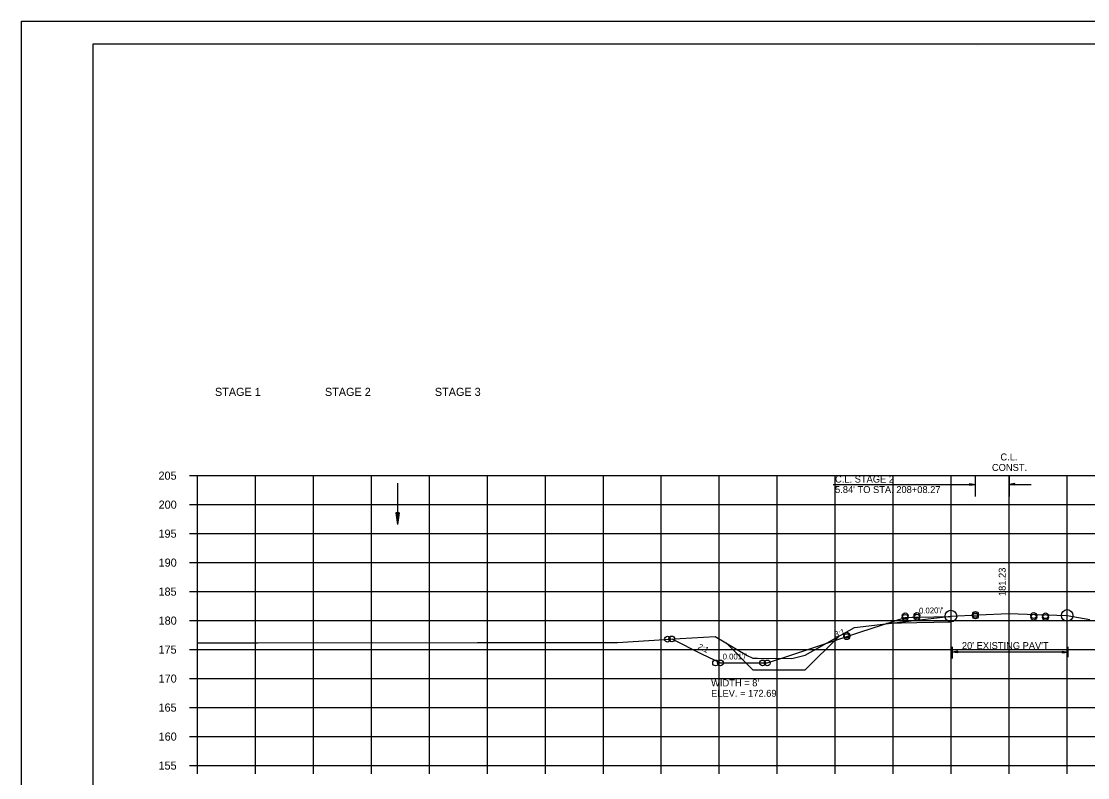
# Model space of a CAD drawing. Extents: x 1372132 to 1372465, y 380083 to 381790.
# Drawn here: x 1372131.6 to 1372315.6, y 381446.4 to 381576.9 of the extents above; entities that cross this region are included whole.
import ezdxf

# ---------------------------------------------------------------- set-up
doc = ezdxf.new("R2010")
doc.units = 0
for name, color, linetype in [('R_Alt Surface', 7, 'Continuous'), ('R_Axis', 7, 'Continuous'), ('R_Axis Annot', 7, 'Continuous'), ('R_Border', 7, 'Continuous'), ('R_Dimension', 7, 'Continuous'), ('R_Draft', 7, 'Continuous'), ('R_Erosion', 7, 'Continuous'), ('R_Exist Surface', 7, 'Continuous'), ('R_Fin Surface', 7, 'Continuous'), ('R_Grid', 7, 'Continuous'), ('R_No Plot', 7, 'Continuous'), ('R_Xsect Elev', 7, 'Continuous'), ('R_Xsect Slope', 7, 'Continuous')]:
    doc.layers.add(name, color=color, linetype=linetype)

msp = doc.modelspace()

# ---------------------------------------------------------------- linework, layer by layer
at = {"layer": 'R_Alt Surface'}
msp.add_lwpolyline([(1372291.96, 381473.22), (1372286.1, 381473.1), (1372280.86, 381473)], dxfattribs=at)
at = {"layer": 'R_Axis'}
for p, q in [((1372160.61, 381498.5), (1372162.01, 381498.5)), ((1372162.01, 381448.5), (1372162.01, 381498.5)), ((1372160.61, 381493.5), (1372162.01, 381493.5)), ((1372160.61, 381488.5), (1372162.01, 381488.5)), ((1372160.61, 381483.5), (1372162.01, 381483.5)), ((1372160.61, 381478.5), (1372162.01, 381478.5)), ((1372160.61, 381473.5), (1372162.01, 381473.5)), ((1372160.61, 381468.5), (1372162.01, 381468.5)), ((1372160.61, 381463.5), (1372162.01, 381463.5)), ((1372160.61, 381458.5), (1372162.01, 381458.5)), ((1372160.61, 381453.5), (1372162.01, 381453.5)), ((1372160.61, 381448.5), (1372162.01, 381448.5)), ((1372162.01, 381448.5), (1372442.01, 381448.5)), ((1372162.01, 381447.1), (1372162.01, 381448.5)), ((1372172.01, 381447.1), (1372172.01, 381448.5)), ((1372182.01, 381447.1), (1372182.01, 381448.5)), ((1372192.01, 381447.1), (1372192.01, 381448.5)), ((1372202.01, 381447.1), (1372202.01, 381448.5)), ((1372212.01, 381447.1), (1372212.01, 381448.5)), ((1372222.01, 381447.1), (1372222.01, 381448.5)), ((1372232.01, 381447.1), (1372232.01, 381448.5)), ((1372242.01, 381447.1), (1372242.01, 381448.5)), ((1372252.01, 381447.1), (1372252.01, 381448.5)), ((1372262.01, 381447.1), (1372262.01, 381448.5)), ((1372272.01, 381447.1), (1372272.01, 381448.5)), ((1372282.01, 381447.1), (1372282.01, 381448.5)), ((1372292.01, 381447.1), (1372292.01, 381448.5)), ((1372302.01, 381447.1), (1372302.01, 381448.5)), ((1372312.01, 381447.1), (1372312.01, 381448.5))]:
    msp.add_line(p, q, dxfattribs=at)
at = {"layer": 'R_Border'}
for p, q in [((1372144.01, 381572.96), (1372460.19, 381572.96)), ((1372144.01, 381367.5), (1372144.01, 381572.96)), ((1372296.53, 381572.7), (1372296.53, 381572.7)), ((1372296.53, 381572.7), (1372296.53, 381572.7))]:
    msp.add_line(p, q, dxfattribs=at)
at = {"layer": 'R_Dimension'}
for p, q in [((1372196.19, 381492.09), (1372196.49, 381490.09)), ((1372196.79, 381492.09), (1372196.19, 381492.09)), ((1372196.19, 381492.09), (1372196.49, 381490.09)), ((1372196.79, 381492.09), (1372196.19, 381492.09)), ((1372196.24, 381492.09), (1372196.49, 381490.42)), ((1372196.24, 381492.09), (1372196.49, 381490.42)), ((1372196.29, 381492.09), (1372196.49, 381490.77)), ((1372196.29, 381492.09), (1372196.49, 381490.77)), ((1372196.34, 381492.09), (1372196.49, 381491.1)), ((1372196.34, 381492.09), (1372196.49, 381491.1)), ((1372196.39, 381492.09), (1372196.49, 381491.44)), ((1372196.39, 381492.09), (1372196.49, 381491.44)), ((1372196.44, 381492.09), (1372196.49, 381491.77)), ((1372196.44, 381492.09), (1372196.49, 381491.77)), ((1372196.79, 381492.09), (1372196.49, 381490.09)), ((1372196.59, 381492.09), (1372196.49, 381491.44)), ((1372196.69, 381492.09), (1372196.49, 381490.77)), ((1372196.74, 381492.09), (1372196.49, 381490.42)), ((1372196.64, 381492.09), (1372196.49, 381491.1)), ((1372196.54, 381492.09), (1372196.49, 381491.77)), ((1372196.79, 381492.09), (1372196.49, 381490.09)), ((1372196.59, 381492.09), (1372196.49, 381491.44)), ((1372196.69, 381492.09), (1372196.49, 381490.77)), ((1372196.74, 381492.09), (1372196.49, 381490.42)), ((1372196.64, 381492.09), (1372196.49, 381491.1)), ((1372196.54, 381492.09), (1372196.49, 381491.77))]:
    msp.add_line(p, q, dxfattribs=at)
at = {"layer": 'R_Draft'}
for p, q in [((1372296.18, 381494.91), (1372296.18, 381498.5)), ((1372302.01, 381498.5), (1372302.01, 381494.91)), ((1372196.49, 381497.23), (1372196.49, 381490.09)), ((1372271.65, 381496.99), (1372296.18, 381496.99)), ((1372295.18, 381497.14), (1372296.18, 381496.99)), ((1372295.18, 381497.14), (1372295.18, 381496.84)), ((1372295.18, 381497.14), (1372296.18, 381496.99)), ((1372295.18, 381497.14), (1372295.18, 381496.84)), ((1372295.18, 381497.11), (1372296.01, 381496.99)), ((1372295.18, 381497.11), (1372296.01, 381496.99)), ((1372295.18, 381497.09), (1372295.84, 381496.99)), ((1372295.18, 381497.09), (1372295.84, 381496.99)), ((1372295.18, 381497.06), (1372295.67, 381496.99)), ((1372295.18, 381497.06), (1372295.67, 381496.99)), ((1372295.18, 381497.04), (1372295.5, 381496.99)), ((1372295.18, 381497.04), (1372295.5, 381496.99)), ((1372295.18, 381497.01), (1372295.34, 381496.99)), ((1372295.18, 381497.01), (1372295.34, 381496.99)), ((1372295.18, 381496.84), (1372296.18, 381496.99)), ((1372295.18, 381496.94), (1372295.5, 381496.99)), ((1372295.18, 381496.89), (1372295.84, 381496.99)), ((1372295.18, 381496.86), (1372296.01, 381496.99)), ((1372295.18, 381496.92), (1372295.67, 381496.99)), ((1372295.18, 381496.97), (1372295.34, 381496.99)), ((1372295.18, 381496.84), (1372296.18, 381496.99)), ((1372295.18, 381496.94), (1372295.5, 381496.99)), ((1372295.18, 381496.89), (1372295.84, 381496.99)), ((1372295.18, 381496.86), (1372296.01, 381496.99)), ((1372295.18, 381496.92), (1372295.67, 381496.99)), ((1372295.18, 381496.97), (1372295.34, 381496.99)), ((1372303.01, 381497.14), (1372302.01, 381496.99)), ((1372302.01, 381496.99), (1372305.82, 381496.99)), ((1372303.01, 381496.84), (1372302.01, 381496.99)), ((1372303.01, 381497.11), (1372302.18, 381496.99)), ((1372303.01, 381496.86), (1372302.18, 381496.99)), ((1372303.01, 381497.09), (1372302.35, 381496.99)), ((1372303.01, 381496.89), (1372302.35, 381496.99)), ((1372303.01, 381497.06), (1372302.52, 381496.99)), ((1372303.01, 381496.92), (1372302.52, 381496.99)), ((1372303.01, 381497.04), (1372302.69, 381496.99)), ((1372303.01, 381496.94), (1372302.69, 381496.99)), ((1372303.01, 381497.01), (1372302.86, 381496.99)), ((1372303.01, 381496.97), (1372302.86, 381496.99)), ((1372303.01, 381496.84), (1372303.01, 381497.14)), ((1372291.96, 381474.22), (1372291.96, 381473.22)), ((1372292.16, 381469), (1372292.16, 381466.98)), ((1372312.14, 381469), (1372312.14, 381467.22)), ((1372293.16, 381468.23), (1372292.16, 381468.08)), ((1372293.16, 381468.23), (1372292.16, 381468.08)), ((1372312.14, 381468.08), (1372292.16, 381468.08)), ((1372293.16, 381467.93), (1372292.16, 381468.08)), ((1372293.16, 381467.93), (1372292.16, 381468.08)), ((1372292.16, 381467.22), (1372292.16, 381467.22)), ((1372293.16, 381468.2), (1372292.33, 381468.08)), ((1372293.16, 381468.2), (1372292.33, 381468.08)), ((1372293.16, 381467.95), (1372292.33, 381468.08)), ((1372293.16, 381467.95), (1372292.33, 381468.08)), ((1372293.16, 381468.18), (1372292.5, 381468.08)), ((1372293.16, 381468.18), (1372292.5, 381468.08)), ((1372293.16, 381467.98), (1372292.5, 381468.08)), ((1372293.16, 381467.98), (1372292.5, 381468.08)), ((1372293.16, 381468.15), (1372292.67, 381468.08)), ((1372293.16, 381468.15), (1372292.67, 381468.08)), ((1372293.16, 381468), (1372292.67, 381468.08)), ((1372293.16, 381468), (1372292.67, 381468.08)), ((1372293.16, 381468.13), (1372292.84, 381468.08)), ((1372293.16, 381468.13), (1372292.84, 381468.08)), ((1372293.16, 381468.03), (1372292.84, 381468.08)), ((1372293.16, 381468.03), (1372292.84, 381468.08)), ((1372293.16, 381468.1), (1372293, 381468.08)), ((1372293.16, 381468.1), (1372293, 381468.08)), ((1372293.16, 381468.06), (1372293, 381468.08)), ((1372293.16, 381468.06), (1372293, 381468.08)), ((1372293.16, 381467.93), (1372293.16, 381468.23)), ((1372293.16, 381467.93), (1372293.16, 381468.23)), ((1372311.14, 381468.23), (1372312.14, 381468.08)), ((1372311.14, 381468.23), (1372311.14, 381467.93)), ((1372311.14, 381468.2), (1372311.97, 381468.08)), ((1372311.14, 381468.18), (1372311.8, 381468.08)), ((1372311.14, 381468.15), (1372311.64, 381468.08)), ((1372311.14, 381468.13), (1372311.47, 381468.08)), ((1372311.14, 381468.1), (1372311.3, 381468.08)), ((1372311.14, 381467.93), (1372312.14, 381468.08)), ((1372311.14, 381468.03), (1372311.47, 381468.08)), ((1372311.14, 381467.98), (1372311.8, 381468.08)), ((1372311.14, 381467.95), (1372311.97, 381468.08)), ((1372311.14, 381468), (1372311.64, 381468.08)), ((1372311.14, 381468.06), (1372311.3, 381468.08))]:
    msp.add_line(p, q, dxfattribs=at)
at = {"layer": 'R_Erosion'}
for p, q in [((1372266.84, 381465), (1372272.67, 381470.83)), ((1372257.8, 381465), (1372253.17, 381469.64)), ((1372257.8, 381465), (1372266.84, 381465))]:
    msp.add_line(p, q, dxfattribs=at)
at = {"layer": 'R_Exist Surface'}
msp.add_lwpolyline([(1372162.01, 381469.65), (1372172.38, 381469.68), (1372210.27, 381469.71), (1372234.47, 381469.73), (1372245.27, 381470.44), (1372251.28, 381470.77), (1372256.79, 381467.47), (1372257.81, 381467), (1372258.61, 381467.01), (1372264.39, 381466.94), (1372264.77, 381467.02), (1372266.84, 381467.52), (1372274.44, 381471.8), (1372275.36, 381472.31), (1372278.77, 381472.74), (1372291.96, 381474.28), (1372296.73, 381474.49), (1372301.93, 381474.73), (1372306.74, 381474.57), (1372312.02, 381474.39), (1372315.9, 381473.71)], dxfattribs=at)
at = {"layer": 'R_Fin Surface'}
msp.add_lwpolyline([(1372243.8, 381470.33), (1372248.96, 381467.79), (1372252.2, 381466.2), (1372255.61, 381466.2), (1372260.29, 381466.2), (1372263.16, 381467.15), (1372270.76, 381469.66), (1372272.81, 381470.34), (1372274, 381470.73), (1372276.28, 381471.48), (1372284.08, 381474.06), (1372285.28, 381474.09), (1372286.1, 381474.1), (1372291.96, 381474.22)], dxfattribs=at)
at = {"layer": 'R_Grid'}
for p, q in [((1372162.01, 381498.5), (1372442.01, 381498.5)), ((1372162.01, 381448.5), (1372162.01, 381498.5)), ((1372172.01, 381448.5), (1372172.01, 381498.5)), ((1372182.01, 381448.5), (1372182.01, 381498.5)), ((1372192.01, 381448.5), (1372192.01, 381498.5)), ((1372202.01, 381448.5), (1372202.01, 381498.5)), ((1372212.01, 381448.5), (1372212.01, 381498.5)), ((1372222.01, 381448.5), (1372222.01, 381498.5)), ((1372232.01, 381448.5), (1372232.01, 381498.5)), ((1372242.01, 381448.5), (1372242.01, 381498.5)), ((1372252.01, 381448.5), (1372252.01, 381498.5)), ((1372262.01, 381448.5), (1372262.01, 381498.5)), ((1372272.01, 381448.5), (1372272.01, 381498.5)), ((1372282.01, 381448.5), (1372282.01, 381498.5)), ((1372292.01, 381448.5), (1372292.01, 381498.5)), ((1372302.01, 381448.5), (1372302.01, 381498.5)), ((1372312.01, 381448.5), (1372312.01, 381498.5)), ((1372162.01, 381493.5), (1372442.01, 381493.5)), ((1372162.01, 381488.5), (1372442.01, 381488.5)), ((1372162.01, 381483.5), (1372442.01, 381483.5)), ((1372162.01, 381478.5), (1372442.01, 381478.5)), ((1372162.01, 381473.5), (1372442.01, 381473.5)), ((1372162.01, 381468.5), (1372442.01, 381468.5)), ((1372162.01, 381463.5), (1372442.01, 381463.5)), ((1372162.01, 381458.5), (1372442.01, 381458.5)), ((1372162.01, 381453.5), (1372442.01, 381453.5)), ((1372162.01, 381448.5), (1372442.01, 381448.5))]:
    msp.add_line(p, q, dxfattribs=at)
at = {"layer": 'R_No Plot'}
msp.add_line((1372131.61, 381576.86), (1372464.95, 381576.86), dxfattribs=at)
for points in [[(1372131.61, 381576.86), (1372464.95, 381576.86), (1372464.95, 381363.52), (1372131.61, 381363.52)], [(1372377.93, 381572.96), (1372377.93, 381563.08), (1372413.67, 381563.08), (1372413.67, 381560.16), (1372436.87, 381560.16), (1372436.87, 381535.83), (1372460.19, 381535.83), (1372460.19, 381367.5), (1372144.01, 381367.5), (1372144.01, 381572.96)]]:
    msp.add_lwpolyline(points, close=True, dxfattribs=at)
for centre, radius in [((1372284.08, 381474.34), 0.5), ((1372284.08, 381474.06), 0.5), ((1372286.1, 381474.38), 0.5), ((1372286.1, 381474.1), 0.5), ((1372291.96, 381474.28), 1), ((1372296.18, 381474.58), 0.5), ((1372296.18, 381474.3), 0.5), ((1372306.26, 381474.38), 0.5), ((1372306.26, 381474.1), 0.5), ((1372308.28, 381474.34), 0.5), ((1372308.28, 381474.06), 0.5), ((1372312.02, 381474.39), 1), ((1372243.07, 381470.29), 0.5), ((1372243.8, 381470.33), 0.5), ((1372273.99, 381471), 0.5), ((1372274, 381470.73), 0.5), ((1372251.37, 381466.19), 0.5), ((1372252.2, 381466.2), 0.5), ((1372259.47, 381466.2), 0.5), ((1372260.29, 381466.2), 0.5)]:
    msp.add_circle(centre, radius, dxfattribs=at)
at = {"layer": 'R_Xsect Elev'}
msp.add_line((1372302.01, 381474.73), (1372302.01, 381484.73), dxfattribs=at)

# ---------------------------------------------------------------- texts
at = {"layer": 'R_Axis Annot'}
for s, p in [('STAGE 1', (1372165.01, 381512.25)), ('STAGE 2', (1372183.98, 381512.25)), ('STAGE 3', (1372202.94, 381512.25)), ('205', (1372155.27, 381497.8)), ('200', (1372155.29, 381492.8)), ('195', (1372155.27, 381487.8)), ('190', (1372155.29, 381482.8)), ('185', (1372155.27, 381477.8)), ('180', (1372155.29, 381472.8)), ('175', (1372155.27, 381467.8)), ('170', (1372155.29, 381462.8)), ('165', (1372155.27, 381457.8)), ('160', (1372155.29, 381452.8)), ('155', (1372155.27, 381447.8))]:
    msp.add_text(s, height=1.4, dxfattribs=at).set_placement(p)
at = {"layer": 'R_Dimension'}
for s, p in [("WIDTH = 8'", (1372250.6, 381462.16)), ('ELEV. = 172.69', (1372250.6, 381460.36))]:
    msp.add_text(s, height=1.2, dxfattribs=at).set_placement(p)
at = {"layer": 'R_Draft'}
for s, p in [('C.L. ', (1372300.51, 381501.12)), ('CONST. ', (1372299.04, 381499.32)), ('C.L. STAGE 2', (1372271.98, 381497.3)), ("5.84' TO STA. 208+08.27", (1372271.98, 381495.5)), ("20' EXISTING PAV'T", (1372293.86, 381468.59))]:
    msp.add_text(s, height=1.2, rotation=360, dxfattribs=at).set_placement(p)
at = {"layer": 'R_Xsect Elev'}
msp.add_text('181.23', height=1.2, rotation=90, dxfattribs=at).set_placement((1372301.41, 381477.73))
at = {"layer": 'R_Xsect Slope'}
for s, rotation, p in [("0.020'/'", 1.1357, (1372286.47, 381474.71)), ('3:1', 18.282, (1372272.03, 381470.61)), ('2:1', 333.7521, (1372248.22, 381468.71)), ("0.001'/'", 0.0507, (1372252.59, 381466.8))]:
    msp.add_text(s, height=1, rotation=rotation, dxfattribs=at).set_placement(p)

doc.saveas('drawing.dxf')
